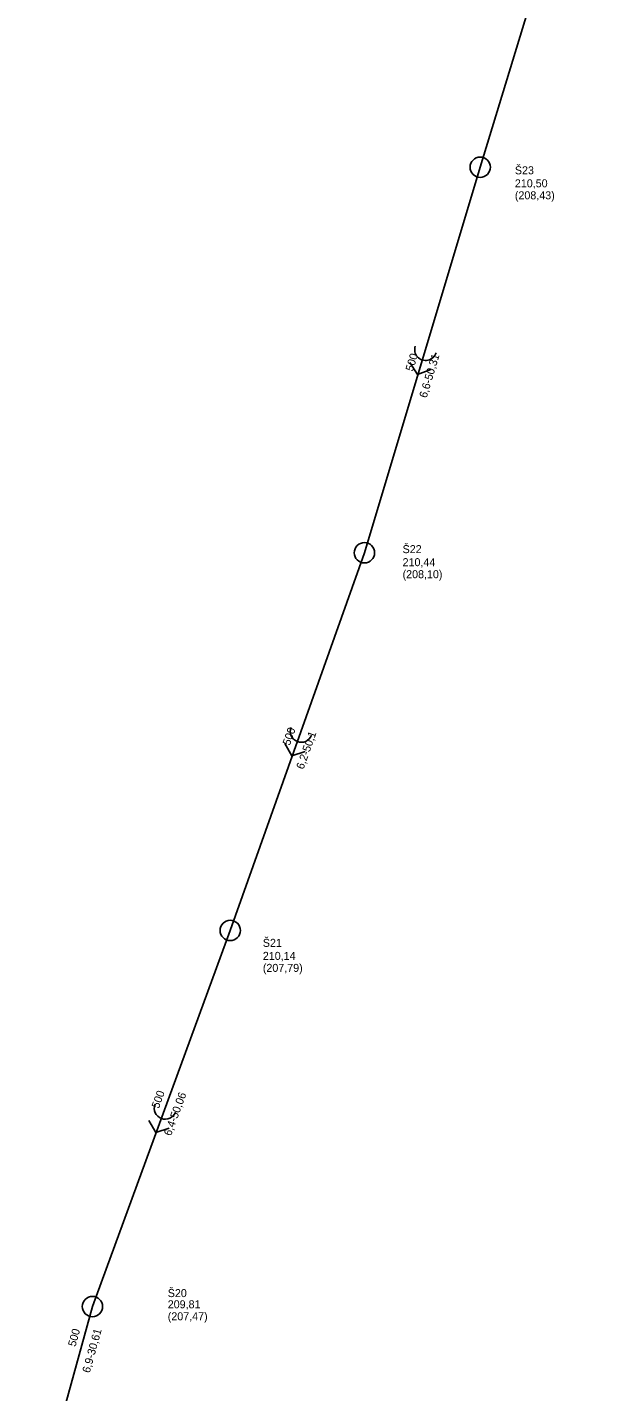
# Model space of a CAD drawing. Extents: x -569540 to -569072, y -1179643 to -1178245.
# Drawn here: x -569512.7 to -569441.8, y -1179294.7 to -1179124.1 of the extents above; entities that cross this region are included whole.
import ezdxf

# ---------------------------------------------------------------- set-up
doc = ezdxf.new("R2010")
doc.units = 0
for name, color, linetype in [('Vrstva 1', 7, 'Continuous'), ('Vrstva 15', 7, 'Continuous'), ('Vrstva 29', 7, 'Continuous'), ('Vrstva 41', 7, 'Continuous'), ('Vrstva 44', 7, 'Continuous'), ('Vrstva 45', 7, 'Continuous'), ('Vrstva 56', 7, 'Continuous'), ('Vrstva 57', 7, 'Continuous')]:
    doc.layers.add(name, color=color, linetype=linetype)

# ---------------------------------------------------------------- blocks, each defined once
blk = doc.blocks.new('100')
at = {"layer": 'Vrstva 1'}
blk.add_circle((0, 0), 1.27, dxfattribs=at)
blk = doc.blocks.new('86')
at = {"layer": 'Vrstva 1'}
blk.add_lwpolyline([(0.79, 1.37), (1.89, 0), (0.79, -1.38)], dxfattribs=at)
blk.add_arc((-1.37, 0), 1.37, 270, 90, dxfattribs=at)

msp = doc.modelspace()

# ---------------------------------------------------------------- linework, layer by layer
at = {"layer": 'Vrstva 15'}
for p, q in [((-569441.84, -1179094.78), (-569456.14, -1179141.64)), ((-569456.14, -1179141.64), (-569470.61, -1179189.83)), ((-569470.61, -1179189.83), (-569487.37, -1179237.04)), ((-569487.37, -1179237.04), (-569504.59, -1179284.05)), ((-569504.59, -1179284.05), (-569512.73, -1179313.56))]:
    msp.add_line(p, q, dxfattribs=at)

# ---------------------------------------------------------------- block references
at = {"layer": 'Vrstva 29'}
for p, xscale, yscale, rotation in [((-569456.14, -1179141.64), 0.9999999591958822, 0.9999999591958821, -107.99999945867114), ((-569470.61, -1179189.83), 0.9999999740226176, 0.9999999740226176, -108.99999960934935), ((-569487.37, -1179237.04), 0.999999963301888, 0.9999999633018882, -110.99999898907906), ((-569504.59, -1179284.05), 0.9999999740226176, 0.9999999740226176, -108.99999960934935)]:
    msp.add_blockref('100', p, dxfattribs=dict(at, xscale=xscale, yscale=yscale, rotation=rotation))
at = {"layer": 'Vrstva 41'}
for p, xscale, yscale, rotation in [((-569463.38, -1179165.73), 0.9999999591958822, 0.9999999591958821, -107.99999945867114), ((-569478.99, -1179213.43), 0.999999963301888, 0.9999999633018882, -110.99999898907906), ((-569495.98, -1179260.54), 0.999999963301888, 0.9999999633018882, -110.99999898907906)]:
    msp.add_blockref('86', p, dxfattribs=dict(at, xscale=xscale, yscale=yscale, rotation=rotation))

# ---------------------------------------------------------------- texts
at = {"layer": 'Vrstva 44'}
for rotation, p in [(73.29, (-569464.55, -1179167.22)), (70.46, (-569479.93, -1179213.99)), (69.88, (-569496.3, -1179259.37)), (74.57, (-569506.71, -1179289.13))]:
    msp.add_text('500', height=1, rotation=rotation, dxfattribs=at).set_placement(p)
at = {"layer": 'Vrstva 45'}
for s, rotation, p in [('6,6-50,31', 73.29, (-569462.84, -1179170.55)), ('6,2-50,1', 70.46, (-569478.23, -1179216.98)), ('6,4-50,06', 69.88, (-569494.78, -1179262.8)), ('6,9-30,61', 74.57, (-569504.93, -1179292.42))]:
    msp.add_text(s, height=1, rotation=rotation, dxfattribs=at).set_placement(p)
at = {"layer": 'Vrstva 56'}
for s, p in [('210,50 ', (-569451.81, -1179144.15)), ('(208,43)', (-569451.81, -1179145.65)), ('210,44 ', (-569465.84, -1179191.51)), ('(208,10)', (-569465.84, -1179193.01)), ('210,14 ', (-569483.3, -1179240.72)), ('(207,79)', (-569483.3, -1179242.22)), ('209,81 ', (-569495.18, -1179284.27)), ('(207,47)', (-569495.18, -1179285.77))]:
    msp.add_text(s, height=1, dxfattribs=at).set_placement(p)
at = {"layer": 'Vrstva 57'}
for s, p in [('Š23', (-569451.81, -1179142.52)), ('Š22', (-569465.84, -1179189.88)), ('Š21', (-569483.3, -1179239.09)), ('Š20', (-569495.18, -1179282.87))]:
    msp.add_text(s, height=1, dxfattribs=at).set_placement(p)

doc.saveas('drawing.dxf')
